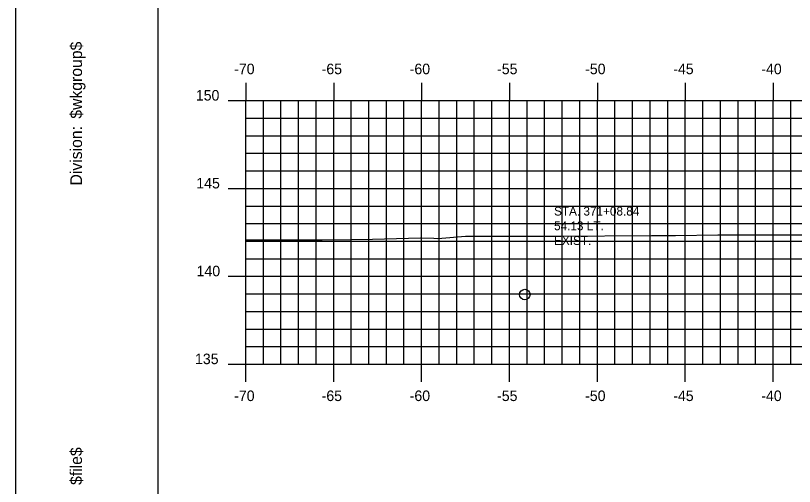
# Model space of a CAD drawing. Extents: x 1148299 to 1148469, y 608981 to 609091.
# Drawn here: x 1148298.63 to 1148342.93, y 609008.38 to 609035.17 of the extents above; entities that cross this region are included whole.
import ezdxf

# ---------------------------------------------------------------- set-up
doc = ezdxf.new("R2010")
doc.units = 0
for name, color, linetype in [('BORDER', 7, 'Continuous'), ('D_Text_Monospaced', 7, 'Continuous'), ('H_V ANNOTATION', 7, 'Continuous'), ('MAJOR', 7, 'Continuous'), ('MINOR', 7, 'Continuous'), ('PLOT BOUNDARY', 7, 'Continuous'), ('S_Drainage_Invert', 7, 'Continuous'), ('S_Roadway_Centerline', 7, 'Continuous')]:
    doc.layers.add(name, color=color, linetype=linetype)

msp = doc.modelspace()

# ---------------------------------------------------------------- linework, layer by layer
at = {"layer": 'BORDER'}
msp.add_lwpolyline([(1148306.724, 608984.335), (1148466.724, 608984.335), (1148466.724, 609089.335), (1148306.724, 609089.335)], close=True, dxfattribs=at)
at = {"layer": 'MAJOR'}
for p, q in [((1148311.724, 609031.337), (1148311.724, 609030.335)), ((1148316.724, 609031.337), (1148316.724, 609030.335)), ((1148321.724, 609031.337), (1148321.724, 609030.335)), ((1148326.724, 609031.337), (1148326.724, 609030.335)), ((1148331.724, 609031.337), (1148331.724, 609030.335)), ((1148336.724, 609031.337), (1148336.724, 609030.335)), ((1148341.724, 609031.337), (1148341.724, 609030.335)), ((1148310.722, 609030.335), (1148311.724, 609030.335)), ((1148311.724, 609030.335), (1148451.724, 609030.335)), ((1148311.724, 609015.335), (1148311.724, 609030.335)), ((1148311.724, 609015.335), (1148311.724, 609030.335)), ((1148311.724, 609030.335), (1148451.724, 609030.335)), ((1148316.724, 609015.335), (1148316.724, 609030.335)), ((1148321.724, 609015.335), (1148321.724, 609030.335)), ((1148326.724, 609015.335), (1148326.724, 609030.335)), ((1148331.724, 609015.335), (1148331.724, 609030.335)), ((1148336.724, 609015.335), (1148336.724, 609030.335)), ((1148341.724, 609015.335), (1148341.724, 609030.335)), ((1148310.722, 609025.335), (1148311.724, 609025.335)), ((1148311.724, 609025.335), (1148451.724, 609025.335)), ((1148310.722, 609020.335), (1148311.724, 609020.335)), ((1148311.724, 609020.335), (1148451.724, 609020.335)), ((1148310.722, 609015.335), (1148311.724, 609015.335)), ((1148311.724, 609015.335), (1148451.724, 609015.335)), ((1148311.724, 609015.335), (1148451.724, 609015.335)), ((1148311.724, 609014.333), (1148311.724, 609015.335)), ((1148316.724, 609014.333), (1148316.724, 609015.335)), ((1148321.724, 609014.333), (1148321.724, 609015.335)), ((1148326.724, 609014.333), (1148326.724, 609015.335)), ((1148331.724, 609014.333), (1148331.724, 609015.335)), ((1148336.724, 609014.333), (1148336.724, 609015.335)), ((1148341.724, 609014.333), (1148341.724, 609015.335))]:
    msp.add_line(p, q, dxfattribs=at)
at = {"layer": 'MINOR'}
for p, q in [((1148312.724, 609015.335), (1148312.724, 609030.335)), ((1148313.724, 609015.335), (1148313.724, 609030.335)), ((1148314.724, 609015.335), (1148314.724, 609030.335)), ((1148315.724, 609015.335), (1148315.724, 609030.335)), ((1148317.724, 609015.335), (1148317.724, 609030.335)), ((1148318.724, 609015.335), (1148318.724, 609030.335)), ((1148319.724, 609015.335), (1148319.724, 609030.335)), ((1148320.724, 609015.335), (1148320.724, 609030.335)), ((1148322.724, 609015.335), (1148322.724, 609030.335)), ((1148323.724, 609015.335), (1148323.724, 609030.335)), ((1148324.724, 609015.335), (1148324.724, 609030.335)), ((1148325.724, 609015.335), (1148325.724, 609030.335)), ((1148327.724, 609015.335), (1148327.724, 609030.335)), ((1148328.724, 609015.335), (1148328.724, 609030.335)), ((1148329.724, 609015.335), (1148329.724, 609030.335)), ((1148330.724, 609015.335), (1148330.724, 609030.335)), ((1148332.724, 609015.335), (1148332.724, 609030.335)), ((1148333.724, 609015.335), (1148333.724, 609030.335)), ((1148334.724, 609015.335), (1148334.724, 609030.335)), ((1148335.724, 609015.335), (1148335.724, 609030.335)), ((1148337.724, 609015.335), (1148337.724, 609030.335)), ((1148338.724, 609015.335), (1148338.724, 609030.335)), ((1148339.724, 609015.335), (1148339.724, 609030.335)), ((1148340.724, 609015.335), (1148340.724, 609030.335)), ((1148342.724, 609015.335), (1148342.724, 609030.335)), ((1148311.724, 609029.335), (1148451.724, 609029.335)), ((1148311.724, 609029.335), (1148312.726, 609029.335)), ((1148311.724, 609028.335), (1148451.724, 609028.335)), ((1148311.724, 609028.335), (1148312.726, 609028.335)), ((1148311.724, 609027.335), (1148451.724, 609027.335)), ((1148311.724, 609027.335), (1148312.726, 609027.335)), ((1148311.724, 609026.335), (1148451.724, 609026.335)), ((1148311.724, 609026.335), (1148312.726, 609026.335)), ((1148311.724, 609024.335), (1148451.724, 609024.335)), ((1148311.724, 609024.335), (1148312.726, 609024.335)), ((1148311.724, 609023.335), (1148451.724, 609023.335)), ((1148311.724, 609023.335), (1148312.726, 609023.335)), ((1148311.724, 609022.335), (1148451.724, 609022.335)), ((1148311.724, 609022.335), (1148312.726, 609022.335)), ((1148311.724, 609021.335), (1148451.724, 609021.335)), ((1148311.724, 609021.335), (1148312.726, 609021.335)), ((1148311.724, 609019.335), (1148451.724, 609019.335)), ((1148311.724, 609019.335), (1148312.726, 609019.335)), ((1148311.724, 609018.335), (1148451.724, 609018.335)), ((1148311.724, 609018.335), (1148312.726, 609018.335)), ((1148311.724, 609017.335), (1148451.724, 609017.335)), ((1148311.724, 609017.335), (1148312.726, 609017.335)), ((1148311.724, 609016.335), (1148451.724, 609016.335)), ((1148311.724, 609016.335), (1148312.726, 609016.335))]:
    msp.add_line(p, q, dxfattribs=at)
at = {"layer": 'PLOT BOUNDARY'}
msp.add_lwpolyline([(1148298.63, 608981.276), (1148468.63, 608981.276), (1148468.63, 609091.276), (1148298.63, 609091.276)], close=True, dxfattribs=at)
at = {"layer": 'S_Drainage_Invert'}
msp.add_circle((1148327.593, 609019.294), 0.3, dxfattribs=at)
at = {"layer": 'S_Roadway_Centerline'}
msp.add_lwpolyline([(1148311.724, 609022.419), (1148313.623, 609022.406), (1148316.069, 609022.407), (1148317.746, 609022.427), (1148318.938, 609022.451), (1148321.659, 609022.529), (1148322.415, 609022.513), (1148322.652, 609022.495), (1148324.228, 609022.622), (1148324.28, 609022.627), (1148325.449, 609022.623), (1148327.272, 609022.618), (1148328.878, 609022.621), (1148329.475, 609022.627), (1148334.81, 609022.647), (1148336.174, 609022.66), (1148338.577, 609022.693), (1148379.772, 609022.685)], dxfattribs=at)

# ---------------------------------------------------------------- texts
at = {"layer": 'BORDER'}
for s, p in [('$wkgroup$', (1148302.409, 609029.305)), ('Division:', (1148302.409, 609025.501)), ('$file$', (1148302.409, 609008.461))]:
    msp.add_text(s, height=0.6696, rotation=90, dxfattribs=at).set_placement(p)
at = {"layer": 'D_Text_Monospaced'}
for s, height, p in [('STA. 371+08.84', 0.49998, (1148329.26, 609023.792)), ('54.13 LT.', 0.5, (1148329.26, 609022.958)), ('EXIST. ', 0.5, (1148329.26, 609022.118))]:
    msp.add_text(s, height=height, dxfattribs=at).set_placement(p)
at = {"layer": 'H_V ANNOTATION'}
for s, p in [('-70', (1148311.065, 609031.835)), ('-65', (1148316.041, 609031.835)), ('-60', (1148321.049, 609031.835)), ('-55', (1148326.02, 609031.835)), ('-50', (1148331.028, 609031.835)), ('-45', (1148336.041, 609031.835)), ('-40', (1148341.049, 609031.835)), ('150', (1148308.885, 609030.335)), ('145', (1148308.912, 609025.335)), ('140', (1148308.928, 609020.335)), ('135', (1148308.838, 609015.335)), ('-70', (1148311.065, 609013.235)), ('-65', (1148316.041, 609013.235)), ('-60', (1148321.049, 609013.235)), ('-55', (1148326.02, 609013.235)), ('-50', (1148331.028, 609013.235)), ('-45', (1148336.041, 609013.235)), ('-40', (1148341.049, 609013.235))]:
    msp.add_text(s, height=0.6, dxfattribs=at).set_placement(p)
at = {"layer": 'MAJOR'}
msp.add_text('-', height=0.006, dxfattribs=at).set_placement((1148311.719, 609015.335))

doc.saveas('drawing.dxf')
